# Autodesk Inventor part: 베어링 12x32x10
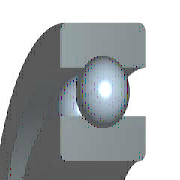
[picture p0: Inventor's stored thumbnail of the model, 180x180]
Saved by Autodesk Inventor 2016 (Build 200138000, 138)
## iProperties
IsCustomPart: 1
Created: 2012-02
Part Number: 베어링 12x32x10
Material: 강철, 연강
Description: 깊은 그루브 볼 베어링
Document SubType Name: Modeling
Standard: KS B 2023
Designer: test
Standards Organization: KS
Language: ko-KR
Size Designation: 6201 - 12 x 32 x 10
Categories: <MemberInstance><Categories><Category DisplayName="샤프트 부품" InternalName="7f7aeb1f-a693-4053-b835-cee3144e0d98" Mnemonic="SHFT"><Category DisplayName="베어링" Inter
Density: 1 g/cm^3
Appearance: 노란색
Author: test
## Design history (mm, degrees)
sketch "스케치" dims "d0" = 5.2 (= -0.26 x WD + 0.26 x BD)
  geometry: L1 (2.4, 11)-(7.6, 11); L2 (5, 11)-(5, 8.4); L3 (5, 11)-(5, 13.6); L4 (3.068, 9.26)-(0, 9.26); L5 (0, 6)-(10, 6); L6 (3.068, 12.74)-(0, 12.74); L7 (0, 16)-(10, 16); L8 (10, 6)-(10, 9.26); L9 (6.932, 9.26)-(10, 9.26); L10 (6.932, 12.74)-(10, 12.74); L11 (10, 16)-(10, 12.74); L12 (-1.4, 0)-(8.4, 0) reference; L13 (0, -0.3)-(0, 5.3) reference
  constraints: 22 end point, 4 point on line, 2 collinear, 2 perpendicular, 2 symmetric about line, 1 midpoint, 1 parallel, 14 other
  dimensions: "d9" = 12 diameter of L5 L12 (= WD); "d11" = 32 diameter of L7 L12 (= BD); "d12" = 10 distance between parallel lines of L8 L13 (= KB); "d13" = 18.52 diameter of L9 L12 (= 0.326 x BD + 0.674 x WD)
revolve "본체" stored, may be unused: angle "d6" = 90 deg
revolve "볼" stored, may be unused: angle "d7" = 90 deg
pattern_circular "IDS_ARRAYBALL[SIMPL:T]" dims angle "d3" = 360 deg
body "Solid1"
fillet "모깎기1" dims "d1" = 0.6 (= KRS)
other parameters: "WD" = 12 [user parameter; used in 5 equation terms], "BD" = 32 [user parameter; used in 5 equation terms], "KB" = 10 [user parameter; used in 1 equation term], "KRS" = 0.6 [user parameter; used in 1 equation term], "d4" = 0, "d5" = 0, "d8" = 0, "d14" = 0, "d15" = 0, "BBA" = 0 [user parameter], "BC0" = 3100000 [user parameter], "BC" = 6890000 [user parameter], "BR" = 16 (= 0.5 x BD) [user parameter], "WR" = 6 (= 0.5 x WD) [user parameter]
